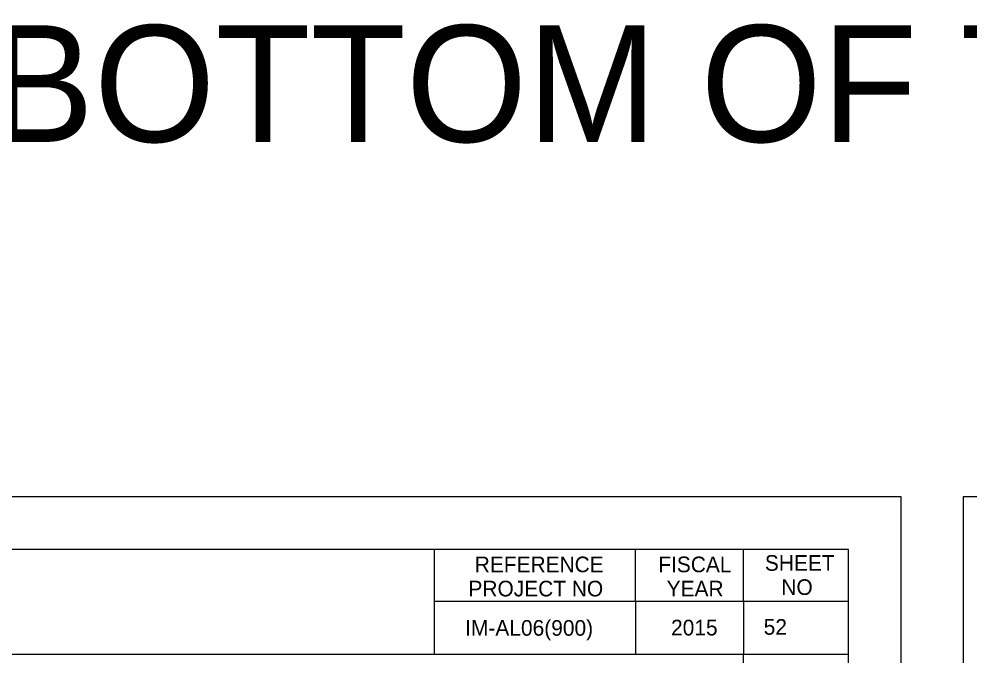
# Model space of a CAD drawing. Extents: x 1797809 to 2198143, y 249608 to 1237864.
# Drawn here: x 2195459.8 to 2195550.3, y 1237322.9 to 1237383.5 of the extents above; entities that cross this region are included whole.
import ezdxf

# ---------------------------------------------------------------- set-up
doc = ezdxf.new("R2010")
doc.units = 0
for name, color, linetype in [('GSCOLORFILL', 7, 'Continuous'), ('GSSHT', 7, 'Continuous'), ('Level 1', 7, 'Continuous'), ('Level 45', 7, 'Continuous'), ('Level 55', 7, 'Continuous'), ('UGUT', 7, 'Continuous')]:
    doc.layers.add(name, color=color, linetype=linetype)

msp = doc.modelspace()

# ---------------------------------------------------------------- linework, layer by layer
at = {"layer": 'GSCOLORFILL'}
msp.add_lwpolyline([(2195216.286, 1237123.036), (2195538.786, 1237123.036), (2195538.786, 1237333.036), (2195216.286, 1237333.036)], close=True, dxfattribs=at)
at = {"layer": 'GSSHT'}
for points in [[(2195203.786, 1237118.036), (2195543.786, 1237118.036), (2195543.786, 1237338.036), (2195203.786, 1237338.036)], [(2195549.71, 1237118.036), (2195889.71, 1237118.036), (2195889.71, 1237338.036), (2195549.71, 1237338.036)]]:
    msp.add_lwpolyline(points, close=True, dxfattribs=at)
at = {"layer": 'Level 45'}
msp.add_lwpolyline([(2195228.783, 1237133.046), (2195528.783, 1237133.046), (2195528.783, 1237323.046), (2195228.783, 1237323.046)], close=True, dxfattribs=at)
at = {"layer": 'UGUT'}
for p, q in [((2195499.33, 1237333.036), (2195499.33, 1237323.046)), ((2195518.493, 1237328.038), (2195518.493, 1237333.038)), ((2195528.783, 1237328.168), (2195528.783, 1237333.038)), ((2195538.786, 1237328.097), (2195499.33, 1237328.097)), ((2195518.493, 1237328.038), (2195518.493, 1237323.046)), ((2195528.783, 1237328.168), (2195528.783, 1237323.046)), ((2195538.786, 1237323.046), (2195500.54, 1237323.046))]:
    msp.add_line(p, q, dxfattribs=at)

# ---------------------------------------------------------------- texts
at = {"layer": 'Level 1'}
for s, height, p in [(' IM-AL06(900) ', 1.48986, (2195501.736, 1237324.827)), ('2015', 1.4899, (2195521.89, 1237324.858)), ('  52 ', 1.4899, (2195529.601, 1237324.918))]:
    msp.add_text(s, height=height, rotation=360, dxfattribs=at).set_placement(p)
at = {"layer": 'Level 55'}
msp.add_text('2) SPECIAL DESIGN POSTS ARE NEEDED BECAUSE THE DISTANCE BETWEEN THE BOTTOM OF THE CENTER', height=11.10462, dxfattribs=at).set_placement((2194857.18, 1237371.809))
at = {"layer": 'UGUT'}
for s, p in [('SHEET', (2195530.82, 1237331.008)), ('REFERENCE', (2195503.203, 1237330.868)), ('FISCAL', (2195520.673, 1237330.868)), ('PROJECT NO', (2195502.603, 1237328.568)), ('YEAR', (2195521.473, 1237328.568)), ('NO', (2195532.39, 1237328.708))]:
    msp.add_text(s, height=1.4883, dxfattribs=at).set_placement(p)

doc.saveas('drawing.dxf')
